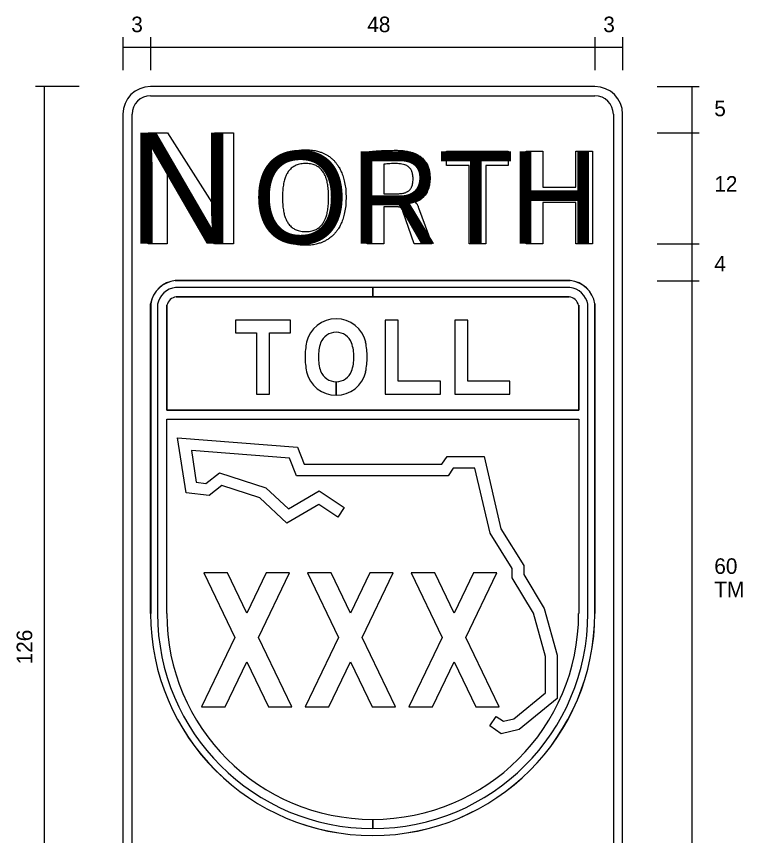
# Model space of a CAD drawing. Extents: x 51788 to 52424, y 9835 to 10249.
# Drawn here: x 51837.4 to 51968.2, y 10083.7 to 10231.3 of the extents above; entities that cross this region are included whole.
import ezdxf

# ---------------------------------------------------------------- set-up
doc = ezdxf.new("R2010")
doc.units = 0
for name, color, linetype in [('GSBWFill', 7, 'Continuous'), ('GSColorFill', 7, 'Continuous'), ('GSDims', 7, 'Continuous'), ('GSOutline', 7, 'Continuous'), ('SignPanel', 7, 'Continuous')]:
    doc.layers.add(name, color=color, linetype=linetype)

msp = doc.modelspace()

# ---------------------------------------------------------------- linework, layer by layer
at = {"layer": 'GSBWFill'}
for p, q in [((51894.99, 10165.5), (51894.99, 10163.1)), ((51894.99, 10163.1), (51894.99, 10165.5))]:
    msp.add_line(p, q, dxfattribs=at)
for points in [[(51876.85, 10174.29), (51880.65, 10174.29), (51880.65, 10163.29), (51882.98, 10163.29), (51882.98, 10174.29), (51886.78, 10174.29), (51886.78, 10176.62), (51876.85, 10176.62)], [(51913.76, 10163.29), (51913.76, 10165.62), (51906.16, 10165.62), (51906.16, 10176.62), (51903.82, 10176.62), (51903.82, 10163.29)], [(51926.3, 10163.29), (51926.3, 10165.62), (51918.7, 10165.62), (51918.7, 10176.62), (51916.37, 10176.62), (51916.37, 10163.29)]]:
    msp.add_lwpolyline(points, close=True, dxfattribs=at)
for centre, radius, start, end in [((51894.92, 10171.45), 5.37, 89.1819, 167.5018), ((51895.07, 10171.45), 5.37, 12.4982, 90.8181), ((51895.02, 10171.39), 3.03, 90.4555, 158.2948), ((51894.97, 10171.39), 3.03, 21.7052, 89.5445), ((51902.57, 10169.89), 13.17, 168.0806, 179.7176), ((51899.95, 10169.97), 8.15, 161.9125, 180.1219), ((51890.04, 10169.97), 8.15, 359.8781, 18.0875), ((51887.42, 10169.89), 13.17, 0.2824, 11.9194), ((51902.57, 10170.02), 13.17, 180.2824, 191.9194), ((51899.95, 10169.94), 8.15, 179.8781, 198.0875), ((51890.04, 10169.94), 8.15, 341.9125, 0.1219), ((51887.42, 10170.02), 13.17, 348.0806, 359.7176), ((51894.92, 10168.46), 5.37, 192.4982, 270.8181), ((51895.02, 10168.53), 3.03, 201.7052, 269.5445), ((51894.97, 10168.53), 3.03, 270.4681, 338.2948), ((51895.07, 10168.46), 5.37, 269.189, 347.5018)]:
    msp.add_arc(centre, radius, start, end, dxfattribs=at)
at = {"layer": 'GSColorFill'}
for p, q in [((51941.58, 10218.7), (51861.58, 10218.7)), ((51861.58, 10217.04), (51941.58, 10217.04)), ((51856.58, 10213.7), (51856.58, 10013.7)), ((51858.25, 10013.7), (51858.25, 10213.7)), ((51944.92, 10213.7), (51944.92, 10013.7)), ((51946.58, 10013.7), (51946.58, 10213.7)), ((51894.99, 10165.5), (51894.99, 10163.1)), ((51894.99, 10163.1), (51894.99, 10165.5))]:
    msp.add_line(p, q, dxfattribs=at)
for points in [[(51937.14, 10183.73), (51866.03, 10183.73)], [(51866.03, 10183.73), (51937.14, 10183.73)], [(51937.14, 10183.72), (51866.03, 10183.72)], [(51866.2, 10180.81), (51901.58, 10180.81), (51901.58, 10182.48), (51866.09, 10182.48)], [(51937.07, 10182.48), (51901.58, 10182.48), (51901.58, 10180.81), (51936.96, 10180.81)], [(51936.96, 10180.81), (51866.2, 10180.81)], [(51861.58, 10179.56), (51861.58, 10123.73)], [(51861.58, 10123.73), (51861.58, 10179.56)], [(51861.6, 10179.56), (51861.6, 10123.73)], [(51862.83, 10179.45), (51862.83, 10123.73)], [(51864.5, 10179.27), (51864.5, 10160.4), (51938.67, 10160.4)], [(51938.67, 10179.27), (51938.67, 10160.4), (51864.5, 10160.4), (51864.5, 10179.27)], [(51938.67, 10160.4), (51938.67, 10179.27)], [(51940.33, 10123.73), (51940.33, 10179.45)], [(51941.57, 10123.73), (51941.57, 10179.56)], [(51941.58, 10123.73), (51941.58, 10179.56)], [(51941.58, 10179.56), (51941.58, 10123.73)], [(51864.5, 10123.73), (51864.5, 10158.73), (51938.67, 10158.73), (51938.67, 10123.73)], [(51901.58, 10084.98), (51901.58, 10086.65)], [(51901.58, 10086.65), (51901.58, 10084.98), (51901.58, 10084.98)], [(51901.58, 10083.73), (51901.58, 10083.74)], [(51901.58, 10083.74), (51901.58, 10083.73)], [(51901.58, 10083.73), (51901.58, 10083.73)]]:
    msp.add_lwpolyline(points, dxfattribs=at)
for points in [[(51876.85, 10174.29), (51880.65, 10174.29), (51880.65, 10163.29), (51882.98, 10163.29), (51882.98, 10174.29), (51886.78, 10174.29), (51886.78, 10176.62), (51876.85, 10176.62)], [(51913.76, 10163.29), (51913.76, 10165.62), (51906.16, 10165.62), (51906.16, 10176.62), (51903.82, 10176.62), (51903.82, 10163.29)], [(51926.3, 10163.29), (51926.3, 10165.62), (51918.7, 10165.62), (51918.7, 10176.62), (51916.37, 10176.62), (51916.37, 10163.29)]]:
    msp.add_lwpolyline(points, close=True, dxfattribs=at)
for centre, radius, start, end in [((51861.58, 10213.7), 5, 90, 180), ((51941.58, 10213.7), 5, 0, 90), ((51861.58, 10213.7), 3.33, 90, 180), ((51941.58, 10213.7), 3.33, 0, 90), ((51866.52, 10178.75), 5, 95.6197, 170.6851), ((51866.52, 10178.75), 5, 95.6197, 170.6851), ((51866.52, 10178.75), 4.99, 95.6272, 170.6726), ((51936.65, 10178.75), 5, 9.3149, 84.3803), ((51936.65, 10178.75), 5, 9.3149, 84.3803), ((51936.65, 10178.75), 4.99, 9.3274, 84.3728), ((51866.52, 10178.75), 3.75, 96.4899, 169.2401), ((51936.65, 10178.75), 3.75, 10.7599, 83.5101), ((51866.52, 10178.75), 2.08, 98.7109, 165.547), ((51866.52, 10178.75), 2.08, 98.7109, 165.547), ((51936.65, 10178.75), 2.08, 14.453, 81.2891), ((51936.65, 10178.75), 2.08, 14.453, 81.2891), ((51894.92, 10171.45), 5.37, 89.1819, 167.5018), ((51895.07, 10171.45), 5.37, 12.4982, 90.8181), ((51895.02, 10171.39), 3.03, 90.4555, 158.2948), ((51894.97, 10171.39), 3.03, 21.7052, 89.5445), ((51902.57, 10169.89), 13.17, 168.0806, 179.7176), ((51899.95, 10169.97), 8.15, 161.9125, 180.1219), ((51890.04, 10169.97), 8.15, 359.8781, 18.0875), ((51887.42, 10169.89), 13.17, 0.2824, 11.9194), ((51902.57, 10170.02), 13.17, 180.2824, 191.9194), ((51899.95, 10169.94), 8.15, 179.8781, 198.0875), ((51890.04, 10169.94), 8.15, 341.9125, 0.1219), ((51887.42, 10170.02), 13.17, 348.0806, 359.7176), ((51894.92, 10168.46), 5.37, 192.4982, 270.8181), ((51895.02, 10168.53), 3.03, 201.7052, 269.5445), ((51894.97, 10168.53), 3.03, 270.4681, 338.2948), ((51895.07, 10168.46), 5.37, 269.189, 347.5018), ((51901.58, 10123.73), 40, 180, 0), ((51901.58, 10123.73), 40, 180, 270), ((51901.58, 10123.73), 39.99, 180, 270), ((51901.58, 10123.73), 38.75, 180, 270), ((51901.58, 10123.73), 37.08, 180, 270), ((51901.58, 10123.73), 38.75, 270.001, 0), ((51901.58, 10123.73), 37.08, 270.001, 360), ((51901.58, 10123.73), 39.99, 270.001, 0), ((51901.58, 10123.73), 40, 270.001, 0)]:
    msp.add_arc(centre, radius, start, end, dxfattribs=at)
at = {"layer": 'GSDims'}
for p, q in [((51856.58, 10227.58), (51856.58, 10221.62)), ((51861.58, 10227.58), (51861.58, 10221.62)), ((51861.58, 10227.58), (51861.58, 10221.62)), ((51941.58, 10227.58), (51941.58, 10221.62)), ((51941.58, 10227.58), (51941.58, 10221.62)), ((51946.58, 10227.58), (51946.58, 10221.62)), ((51856.58, 10225.79), (51861.58, 10225.79)), ((51861.58, 10225.79), (51941.58, 10225.79)), ((51941.58, 10225.79), (51946.58, 10225.79)), ((51848.7, 10218.7), (51840.85, 10218.7)), ((51842.45, 10008.7), (51842.45, 10218.7)), ((51952.83, 10218.7), (51960.38, 10218.7)), ((51959.08, 10008.7), (51959.08, 10218.7)), ((51952.83, 10210.37), (51960.38, 10210.37)), ((51952.83, 10190.37), (51960.38, 10190.37)), ((51952.83, 10183.7), (51960.38, 10183.7)), ((51871.16, 10131.06), (51876.77, 10119.43)), ((51875.4, 10131.06), (51871.16, 10131.06)), ((51878.89, 10123.82), (51875.4, 10131.06)), ((51882.37, 10131.06), (51878.89, 10123.82)), ((51881, 10119.43), (51886.61, 10131.06)), ((51886.61, 10131.06), (51882.37, 10131.06)), ((51889.83, 10131.06), (51895.44, 10119.43)), ((51894.07, 10131.06), (51889.83, 10131.06)), ((51897.56, 10123.82), (51894.07, 10131.06)), ((51901.05, 10131.06), (51897.56, 10123.82)), ((51899.67, 10119.43), (51905.28, 10131.06)), ((51905.28, 10131.06), (51901.05, 10131.06)), ((51908.51, 10131.06), (51914.11, 10119.43)), ((51912.74, 10131.06), (51908.51, 10131.06)), ((51916.23, 10123.82), (51912.74, 10131.06)), ((51919.72, 10131.06), (51916.23, 10123.82)), ((51918.35, 10119.43), (51923.95, 10131.06)), ((51923.95, 10131.06), (51919.72, 10131.06)), ((51876.77, 10119.43), (51870.74, 10106.93)), ((51887.03, 10106.93), (51881, 10119.43)), ((51895.44, 10119.43), (51889.42, 10106.93)), ((51905.7, 10106.93), (51899.67, 10119.43)), ((51914.11, 10119.43), (51908.09, 10106.93)), ((51924.37, 10106.93), (51918.35, 10119.43)), ((51874.98, 10106.93), (51878.89, 10115.03)), ((51878.89, 10115.03), (51882.79, 10106.93)), ((51893.65, 10106.93), (51897.56, 10115.03)), ((51897.56, 10115.03), (51901.46, 10106.93)), ((51912.32, 10106.93), (51916.23, 10115.03)), ((51916.23, 10115.03), (51920.14, 10106.93)), ((51870.74, 10106.93), (51874.98, 10106.93)), ((51882.79, 10106.93), (51887.03, 10106.93)), ((51889.42, 10106.93), (51893.65, 10106.93)), ((51901.46, 10106.93), (51905.7, 10106.93)), ((51908.09, 10106.93), (51912.32, 10106.93)), ((51920.14, 10106.93), (51924.37, 10106.93))]:
    msp.add_line(p, q, dxfattribs=at)
for points in [[(51873.08, 10190.37), (51864.63, 10203.77), (51864.58, 10203.77), (51864.58, 10190.37), (51861.15, 10190.37), (51861.15, 10210.37), (51864.63, 10210.37), (51873.03, 10197.11), (51873.08, 10197.11), (51873.08, 10210.37), (51876.53, 10210.37), (51876.53, 10190.37), (51873.08, 10190.37)], [(51906.11, 10196.99), (51903.59, 10196.99), (51903.59, 10190.37), (51900.6, 10190.37), (51900.6, 10206.93)], [(51921.92, 10204.47), (51921.92, 10190.37), (51918.92, 10190.37), (51918.92, 10204.47), (51914.86, 10204.47), (51914.86, 10207.04), (51926, 10207.04), (51926, 10204.47), (51921.92, 10204.47)], [(51938.15, 10190.37), (51938.15, 10197.78), (51932.22, 10197.78), (51932.22, 10190.37), (51929.22, 10190.37), (51929.22, 10207.04), (51932.22, 10207.04), (51932.22, 10200.58), (51938.15, 10200.58), (51938.15, 10207.04), (51941.15, 10207.04), (51941.15, 10190.37), (51938.15, 10190.37)], [(51903.59, 10204.71), (51903.59, 10199.38), (51906.09, 10199.38)], [(51909.24, 10197.82), (51909.24, 10197.79)], [(51909.04, 10190.37), (51907.01, 10196.23)], [(51909.84, 10196.84), (51912.21, 10190.37), (51909.04, 10190.37)]]:
    msp.add_lwpolyline(points, dxfattribs=at)
for points in [[(51882.22, 10198.72), (51882.22, 10199.04), (51882.24, 10199.95), (51882.39, 10201.13), (51882.67, 10202.24), (51882.97, 10203.13), (51883.35, 10203.94), (51883.76, 10204.57), (51884.05, 10204.96), (51884.37, 10205.33), (51884.79, 10205.74), (51885.37, 10206.18), (51885.89, 10206.48), (51886.33, 10206.7), (51886.8, 10206.89), (51887.56, 10207.12), (51888.51, 10207.28), (51889.21, 10207.29), (51889.5, 10207.3)], [(51889.5, 10207.3), (51889.79, 10207.29), (51890.49, 10207.28), (51891.44, 10207.12), (51892.19, 10206.89), (51892.66, 10206.7), (51893.11, 10206.48), (51893.63, 10206.18), (51894.2, 10205.74), (51894.63, 10205.33), (51894.94, 10204.96), (51895.23, 10204.57), (51895.64, 10203.94), (51896.03, 10203.13), (51896.33, 10202.24), (51896.6, 10201.13), (51896.76, 10199.95), (51896.77, 10199.04), (51896.78, 10198.72)], [(51900.6, 10206.93), (51901.03, 10206.98), (51901.89, 10207.07), (51903.19, 10207.15), (51904.48, 10207.19), (51905.35, 10207.2), (51905.79, 10207.2)], [(51905.79, 10207.2), (51906, 10207.2), (51906.6, 10207.19), (51907.39, 10207.1), (51908.15, 10206.96), (51908.77, 10206.79), (51909.36, 10206.56), (51909.82, 10206.31), (51910.1, 10206.13), (51910.37, 10205.93), (51910.68, 10205.65), (51911.01, 10205.26), (51911.25, 10204.91), (51911.42, 10204.6), (51911.57, 10204.27), (51911.72, 10203.81), (51911.87, 10203.1), (51911.89, 10202.57), (51911.9, 10202.24)], [(51889.5, 10204.81), (51889.4, 10204.81), (51889.12, 10204.8), (51888.66, 10204.76), (51888.15, 10204.65), (51887.76, 10204.5), (51887.48, 10204.36), (51887.22, 10204.2), (51886.91, 10203.97), (51886.59, 10203.65), (51886.36, 10203.35), (51886.19, 10203.09), (51885.91, 10202.58), (51885.68, 10201.93), (51885.48, 10200.95), (51885.36, 10199.96), (51885.34, 10199.14), (51885.34, 10198.72)], [(51893.64, 10198.72), (51893.63, 10199.14), (51893.61, 10199.97), (51893.49, 10200.97), (51893.31, 10201.87), (51893.12, 10202.45), (51892.9, 10202.9), (51892.78, 10203.1), (51892.62, 10203.36), (51892.39, 10203.66), (51892.07, 10203.98), (51891.77, 10204.21), (51891.51, 10204.36), (51891.24, 10204.51), (51890.85, 10204.65), (51890.34, 10204.76), (51889.89, 10204.8), (51889.6, 10204.81), (51889.5, 10204.81)], [(51905.83, 10204.81), (51905.63, 10204.81), (51905.25, 10204.81), (51904.69, 10204.79), (51904.14, 10204.75), (51903.78, 10204.72), (51903.59, 10204.71)], [(51908.84, 10202.07), (51908.84, 10202.19), (51908.83, 10202.52), (51908.78, 10202.91), (51908.69, 10203.25), (51908.61, 10203.47), (51908.49, 10203.71), (51908.35, 10203.92), (51908.21, 10204.08), (51908.09, 10204.19), (51907.96, 10204.29), (51907.74, 10204.43), (51907.37, 10204.6), (51906.83, 10204.74), (51906.29, 10204.8), (51905.95, 10204.81), (51905.83, 10204.81)], [(51906.09, 10199.38), (51906.2, 10199.38), (51906.5, 10199.39), (51906.9, 10199.43), (51907.22, 10199.5), (51907.43, 10199.56), (51907.62, 10199.64), (51907.84, 10199.75), (51908, 10199.86), (51908.12, 10199.96), (51908.24, 10200.07), (51908.37, 10200.22), (51908.5, 10200.43), (51908.59, 10200.62), (51908.66, 10200.79), (51908.77, 10201.13), (51908.83, 10201.56), (51908.84, 10201.95), (51908.84, 10202.07)], [(51911.9, 10202.24), (51911.9, 10202.1), (51911.89, 10201.71), (51911.82, 10201.08), (51911.67, 10200.39), (51911.46, 10199.86), (51911.26, 10199.48), (51911.03, 10199.12), (51910.68, 10198.72), (51910.17, 10198.3), (51909.67, 10198.01), (51909.35, 10197.87), (51909.24, 10197.82)], [(51889.5, 10190.09), (51889.21, 10190.09), (51888.51, 10190.11), (51887.56, 10190.27), (51886.81, 10190.5), (51886.34, 10190.69), (51885.9, 10190.9), (51885.38, 10191.21), (51884.81, 10191.65), (51884.38, 10192.06), (51884.06, 10192.43), (51883.76, 10192.81), (51883.36, 10193.45), (51882.97, 10194.27), (51882.67, 10195.15), (51882.39, 10196.27), (51882.24, 10197.47), (51882.22, 10198.4), (51882.22, 10198.72)], [(51885.34, 10198.72), (51885.34, 10198.29), (51885.36, 10197.47), (51885.48, 10196.46), (51885.66, 10195.55), (51885.86, 10194.97), (51886.08, 10194.51), (51886.2, 10194.3), (51886.37, 10194.03), (51886.6, 10193.73), (51886.92, 10193.4), (51887.23, 10193.17), (51887.49, 10193.01), (51887.77, 10192.87), (51888.16, 10192.72), (51888.67, 10192.61), (51889.13, 10192.56), (51889.42, 10192.56), (51889.52, 10192.56)], [(51896.78, 10198.72), (51896.77, 10198.4), (51896.76, 10197.47), (51896.6, 10196.27), (51896.33, 10195.15), (51896.02, 10194.27), (51895.64, 10193.45), (51895.22, 10192.81), (51894.92, 10192.43), (51894.61, 10192.06), (51894.17, 10191.65), (51893.6, 10191.21), (51893.08, 10190.9), (51892.64, 10190.69), (51892.17, 10190.5), (51891.42, 10190.27), (51890.48, 10190.11), (51889.79, 10190.09), (51889.5, 10190.09)], [(51889.52, 10192.56), (51889.62, 10192.56), (51889.9, 10192.56), (51890.35, 10192.61), (51890.86, 10192.73), (51891.24, 10192.87), (51891.52, 10193.02), (51891.78, 10193.18), (51892.08, 10193.42), (51892.4, 10193.74), (51892.63, 10194.05), (51892.83, 10194.38), (51893.09, 10194.91), (51893.31, 10195.56), (51893.49, 10196.47), (51893.61, 10197.47), (51893.63, 10198.29), (51893.64, 10198.72)], [(51909.24, 10197.79), (51909.25, 10197.79), (51909.28, 10197.77), (51909.32, 10197.75), (51909.37, 10197.72), (51909.43, 10197.67), (51909.5, 10197.59), (51909.56, 10197.49), (51909.64, 10197.33), (51909.74, 10197.12), (51909.81, 10196.93), (51909.84, 10196.84)], [(51907.01, 10196.23), (51906.99, 10196.29), (51906.94, 10196.44), (51906.85, 10196.62), (51906.77, 10196.75), (51906.72, 10196.81), (51906.68, 10196.85), (51906.64, 10196.88), (51906.58, 10196.91), (51906.5, 10196.94), (51906.38, 10196.98), (51906.24, 10196.99), (51906.14, 10196.99), (51906.11, 10196.99)]]:
    msp.add_open_spline(points, degree=3, dxfattribs=at)
at = {"layer": 'GSOutline'}
for points in [[(51876.85, 10174.29), (51880.65, 10174.29), (51880.65, 10163.29), (51882.98, 10163.29), (51882.98, 10174.29), (51886.78, 10174.29), (51886.78, 10176.62), (51876.85, 10176.62)], [(51913.76, 10163.29), (51913.76, 10165.62), (51906.16, 10165.62), (51906.16, 10176.62), (51903.82, 10176.62), (51903.82, 10163.29)], [(51926.3, 10163.29), (51926.3, 10165.62), (51918.7, 10165.62), (51918.7, 10176.62), (51916.37, 10176.62), (51916.37, 10163.29)]]:
    msp.add_lwpolyline(points, close=True, dxfattribs=at)
for centre, radius, start, end in [((51894.92, 10171.45), 5.37, 89.1819, 167.5018), ((51895.07, 10171.45), 5.37, 12.4982, 90.8181), ((51895.02, 10171.39), 3.03, 90.4555, 158.2948), ((51894.97, 10171.39), 3.03, 21.7052, 89.5445), ((51902.57, 10169.89), 13.17, 168.0806, 179.7176), ((51899.95, 10169.97), 8.15, 161.9125, 180.1219), ((51890.04, 10169.97), 8.15, 359.8781, 18.0875), ((51887.42, 10169.89), 13.17, 0.2824, 11.9194), ((51902.57, 10170.02), 13.17, 180.2824, 191.9194), ((51899.95, 10169.94), 8.15, 179.8781, 198.0875), ((51890.04, 10169.94), 8.15, 341.9125, 0.1219), ((51887.42, 10170.02), 13.17, 348.0806, 359.7176), ((51894.92, 10168.46), 5.37, 192.4982, 270.8181), ((51895.02, 10168.53), 3.03, 201.7052, 269.5445), ((51894.97, 10168.53), 3.03, 270.4555, 338.2948), ((51895.07, 10168.46), 5.37, 269.1819, 347.5018)]:
    msp.add_arc(centre, radius, start, end, dxfattribs=at)
at = {"layer": 'SignPanel'}
for p, q in [((51867.99, 10145.51), (51866.45, 10155.4)), ((51866.45, 10155.4), (51888.05, 10153.73)), ((51886.59, 10151.75), (51868.92, 10153.12)), ((51868.92, 10153.12), (51869.81, 10147.39)), ((51888.05, 10153.73), (51889.26, 10150.62)), ((51887.84, 10148.54), (51886.59, 10151.75)), ((51914.04, 10150.62), (51914.97, 10152)), ((51914.97, 10152), (51921.64, 10152)), ((51921.64, 10152), (51924.66, 10139.01)), ((51889.26, 10150.62), (51914.04, 10150.62)), ((51871.52, 10147.18), (51873.97, 10149.11)), ((51873.97, 10149.11), (51882.31, 10146.4)), ((51916.08, 10149.92), (51915.15, 10148.54)), ((51919.99, 10149.92), (51916.08, 10149.92)), ((51922.71, 10138.21), (51919.99, 10149.92)), ((51869.81, 10147.39), (51871.52, 10147.18)), ((51915.15, 10148.54), (51887.84, 10148.54)), ((51874.39, 10146.78), (51872.13, 10145)), ((51881.23, 10144.56), (51874.39, 10146.78)), ((51882.31, 10146.4), (51886.4, 10142.61)), ((51886.4, 10142.61), (51891.94, 10145.87)), ((51891.94, 10145.87), (51896.46, 10142.81)), ((51872.13, 10145), (51867.99, 10145.51)), ((51886.12, 10140.03), (51881.23, 10144.56)), ((51891.87, 10143.4), (51886.12, 10140.03)), ((51895.29, 10141.09), (51891.87, 10143.4)), ((51896.46, 10142.81), (51895.29, 10141.09)), ((51924.66, 10139.01), (51928.77, 10132.41)), ((51926.68, 10131.82), (51922.71, 10138.21)), ((51926.68, 10130.16), (51926.68, 10131.82)), ((51928.77, 10132.41), (51928.77, 10130.75)), ((51930.55, 10123.8), (51926.68, 10130.16)), ((51928.77, 10130.75), (51932.48, 10124.63)), ((51932.69, 10115.97), (51930.55, 10123.8)), ((51932.48, 10124.63), (51934.77, 10116.25)), ((51934.77, 10116.25), (51934.77, 10108.43)), ((51932.69, 10109.42), (51932.69, 10115.97)), ((51927, 10104.75), (51932.69, 10109.42)), ((51934.77, 10108.43), (51927.95, 10102.84)), ((51922.65, 10103.49), (51923.84, 10105.2)), ((51923.84, 10105.2), (51925.13, 10104.31)), ((51925.13, 10104.31), (51927, 10104.75)), ((51924.71, 10102.06), (51922.65, 10103.49)), ((51927.95, 10102.84), (51924.71, 10102.06))]:
    msp.add_line(p, q, dxfattribs=at)

# ---------------------------------------------------------------- texts
at = {"layer": 'GSDims'}
for s, height, p in [('3', 2.8, (51858.1, 10228.49)), ('48', 2.8, (51900.6, 10228.49)), ('3', 2.8, (51943.1, 10228.49)), ('5', 2.8, (51963.09, 10213.34)), ('N', 20, (51857.55, 10190.37)), ('N', 20, (51857.55, 10190.37)), ('O', 16.67, (51879.89, 10190.37)), ('O', 16.67, (51879.89, 10190.37)), ('R', 16.67, (51897.6, 10190.37)), ('R', 16.67, (51897.6, 10190.37)), ('T', 16.67, (51913.35, 10190.37)), ('T', 16.67, (51913.35, 10190.37)), ('H', 16.67, (51926.22, 10190.37)), ('H', 16.67, (51926.22, 10190.37)), ('12', 2.8, (51963.09, 10199.75)), ('4', 2.8, (51963.09, 10185.38)), ('60', 2.8, (51963.09, 10130.88)), ('TM', 2.8, (51963.09, 10126.68))]:
    msp.add_text(s, height=height, dxfattribs=at).set_placement(p)
msp.add_text('126', height=2.8, rotation=90, dxfattribs=at).set_placement((51840.26, 10114.57))

doc.saveas('drawing.dxf')
